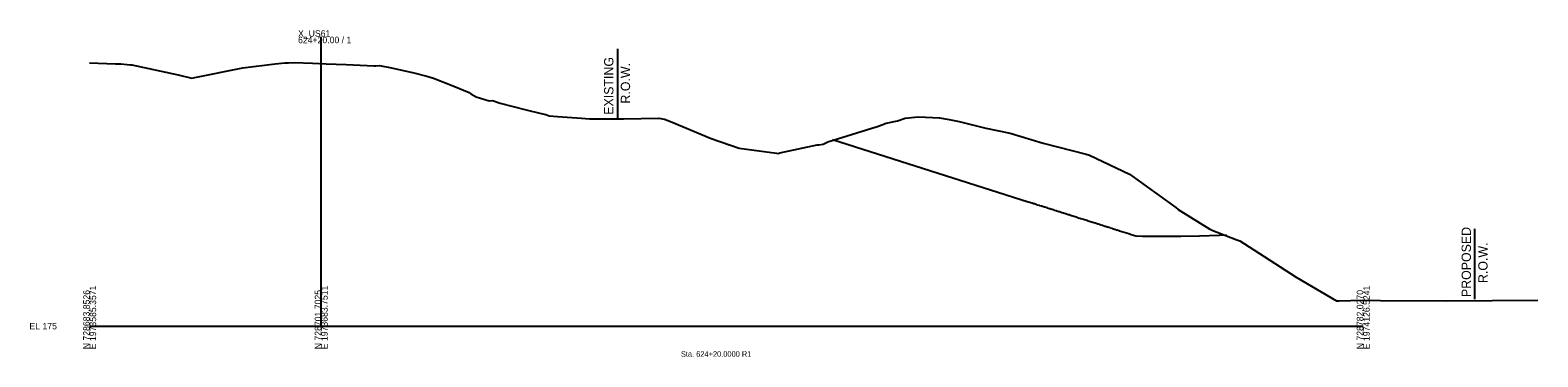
# Model space of a CAD drawing. Extents: x -26 to 1629, y -25 to 9635.
# Drawn here: x 974 to 1625, y 487 to 628 of the extents above; entities that cross this region are included whole.
import ezdxf

# ---------------------------------------------------------------- set-up
doc = ezdxf.new("R2010")
doc.units = 0
for name, color, linetype in [('Draft_XS_Grid', 7, 'Continuous'), ('Draft_XS_Text', 7, 'Continuous'), ('DTM_X_GROUND', 7, 'Continuous'), ('XS_CELL', 7, 'Continuous'), ('XS_P_GROUND', 7, 'Continuous'), ('XS_P_ROW', 7, 'Continuous'), ('XS_X_ROW', 7, 'Continuous')]:
    doc.layers.add(name, color=color, linetype=linetype)

msp = doc.modelspace()

# ---------------------------------------------------------------- linework, layer by layer
at = {"layer": 'DTM_X_GROUND'}
msp.add_lwpolyline([(1000, 613.66), (1011.1, 613.34), (1013.43, 613.27), (1016.14, 613.05), (1017.6, 612.92), (1018.16, 612.86), (1038.23, 608.55), (1044.07, 607.03), (1045.47, 607.34), (1066.13, 611.58), (1080.12, 613.28), (1084.36, 613.68), (1085.9, 613.74), (1088.33, 613.84), (1096.23, 613.57), (1102.11, 613.36), (1110.84, 612.96), (1122.88, 612.41), (1123.55, 612.45), (1125.17, 612.51), (1130.34, 611.53), (1140.05, 609.47), (1145.65, 607.95), (1148.53, 607.16), (1157.2, 603.58), (1163.95, 600.88), (1164.61, 600.26), (1166.94, 599.06), (1172.54, 597.24), (1174.02, 597.39), (1177.3, 596.24), (1188.5, 593.35), (1194.95, 591.78), (1197.02, 591.35), (1198.38, 590.8), (1202.11, 590.54), (1212.35, 589.83), (1215.89, 589.57), (1223.5, 589.54), (1226.67, 589.6), (1227.21, 589.54), (1230.69, 589.6), (1245.81, 589.77), (1248.27, 589.36), (1251.61, 588.09), (1268.33, 581), (1280.45, 576.82), (1281.46, 576.69), (1291.23, 575.37), (1296.62, 574.67), (1297.28, 574.57), (1298.08, 574.81), (1314.15, 578.25), (1314.84, 578.29), (1316.73, 578.66), (1318.77, 579.53), (1339.61, 586.02), (1340.19, 586.17), (1343.92, 587.62), (1348.86, 588.67), (1352.14, 589.81), (1356.33, 590.26), (1357.98, 590.35), (1367.03, 589.99), (1367.03, 589.99), (1371.19, 589.26), (1375.53, 588.32), (1387.04, 585.56), (1387.73, 585.42), (1391.84, 584.55), (1397.54, 583.33), (1411.74, 579.05), (1430.32, 574.26), (1431.77, 573.79), (1449, 565.57), (1469.04, 551.19), (1470.02, 550.38), (1483.78, 541.87), (1484.27, 541.66), (1484.35, 541.63), (1495.47, 537.24), (1496.65, 536.89), (1496.75, 536.87), (1502.68, 532.9), (1521.09, 521.19), (1538.46, 510.96), (1539.62, 510.98), (1549.52, 511.16), (1557.4, 511.07), (1585.97, 510.96), (1625.4, 511.19)], dxfattribs=at)
at = {"layer": 'XS_CELL'}
for p, q in [((1100, 500), (1100, 625)), ((1000, 500), (1100, 500)), ((1100, 500), (1550, 500))]:
    msp.add_line(p, q, dxfattribs=at)
at = {"layer": 'XS_P_GROUND'}
msp.add_lwpolyline([(1490.9, 539.24), (1487.85, 539.1), (1487.8, 539.1), (1479.35, 538.83), (1471.22, 538.68), (1471.07, 538.68), (1462.99, 538.65), (1462.89, 538.65), (1454.72, 538.75), (1454.67, 538.75), (1451.83, 538.84), (1451.81, 538.84), (1450.84, 539.15), (1450.8, 539.16), (1449.82, 539.47), (1449.79, 539.48), (1448.8, 539.8), (1448.78, 539.8), (1447.78, 540.12), (1447.77, 540.12), (1446.76, 540.44), (1446.76, 540.44), (1446.71, 540.46), (1445.75, 540.76), (1445.72, 540.77), (1444.74, 541.08), (1444.72, 541.09), (1444.49, 541.16), (1444.43, 541.18), (1443.73, 541.4), (1443.72, 541.41), (1443.6, 541.45), (1443.5, 541.48), (1442.72, 541.72), (1442.58, 541.77), (1441.71, 542.04), (1441.54, 542.1), (1440.7, 542.37), (1440.5, 542.43), (1439.69, 542.69), (1439.46, 542.76), (1438.68, 543.01), (1438.42, 543.09), (1437.67, 543.33), (1437.38, 543.42), (1436.66, 543.65), (1436.35, 543.75), (1435.65, 543.97), (1435.31, 544.08), (1434.64, 544.29), (1434.28, 544.4), (1433.63, 544.61), (1433.24, 544.73), (1432.62, 544.93), (1432.21, 545.06), (1431.61, 545.25), (1431.18, 545.39), (1430.6, 545.57), (1430.15, 545.71), (1429.59, 545.89), (1429.12, 546.04), (1428.58, 546.21), (1428.09, 546.37), (1427.57, 546.53), (1427.06, 546.69), (1426.56, 546.85), (1426.03, 547.02), (1425.55, 547.17), (1425, 547.35), (1424.54, 547.49), (1423.98, 547.67), (1423.53, 547.81), (1422.95, 548), (1422.52, 548.13), (1421.91, 548.33), (1421.51, 548.45), (1420.87, 548.66), (1420.5, 548.78), (1419.82, 548.99), (1419.49, 549.1), (1418.78, 549.32), (1418.48, 549.42), (1417.73, 549.65), (1417.47, 549.74), (1417.37, 549.77), (1417.34, 549.78), (1416.65, 550), (1416.46, 550.06), (1415.63, 550.32), (1415.45, 550.38), (1414.58, 550.65), (1414.44, 550.7), (1413.53, 550.99), (1413.43, 551.02), (1412.48, 551.32), (1412.42, 551.34), (1411.42, 551.66), (1411.41, 551.66), (1411.08, 551.76), (1410.4, 551.98), (1410.22, 552.04), (1409.39, 552.3), (1408.89, 552.46), (1408.38, 552.62), (1407.98, 552.75), (1407.63, 552.86), (1407.51, 552.9), (1407.37, 552.94), (1407.03, 553.05), (1406.36, 553.26), (1406.08, 553.35), (1405.35, 553.58), (1320.83, 580.4)], dxfattribs=at)
at = {"layer": 'XS_P_ROW'}
msp.add_line((1598, 541.96), (1598, 511.64), dxfattribs=at)
at = {"layer": 'XS_X_ROW'}
msp.add_line((1228, 619.75), (1228, 589.85), dxfattribs=at)

# ---------------------------------------------------------------- texts
at = {"layer": 'Draft_XS_Grid'}
msp.add_text('-', height=0.0001, dxfattribs=at).set_placement((1000, 500))
at = {"layer": 'Draft_XS_Text'}
msp.add_text('Sta. 624+20.0000 R1', height=2.4, dxfattribs=at).set_placement((1255.34, 486.75))
at = {"layer": 'XS_CELL'}
for s, p in [('X_US61', (1090, 625)), ('624+20.00 / 1', (1090, 622.2)), ('EL 175', (974, 498.6))]:
    msp.add_text(s, height=2.8, dxfattribs=at).set_placement(p)
for s, p in [('N 728683.8526', (1000, 490)), ('E 1973585.3571', (1002.8, 490)), ('N 728701.7025', (1100, 490)), ('E 1973683.7511', (1102.8, 490)), ('N 728782.0270', (1550, 490)), ('E 1974126.5241', (1552.8, 490))]:
    msp.add_text(s, height=2.8, rotation=90, dxfattribs=at).set_placement(p)
at = {"layer": 'XS_P_ROW'}
for s, p in [('PROPOSED', (1596.48, 512.53)), ('R.O.W.', (1603.68, 518.6))]:
    msp.add_text(s, height=4, rotation=90, dxfattribs=at).set_placement(p)
at = {"layer": 'XS_X_ROW'}
for s, p in [('EXISTING', (1226.18, 591.29)), ('R.O.W.', (1233.38, 596.13))]:
    msp.add_text(s, height=4, rotation=90, dxfattribs=at).set_placement(p)

doc.saveas('drawing.dxf')
